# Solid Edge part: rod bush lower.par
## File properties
Author: Robert a Rhodes jr
Template: Normal.par
Last saved by: CADCIM
Revision: 11
Application: Solid Edge
Accuracy: 0.99
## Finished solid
Body 1: solid body, 4 faces, 4 edges, 0 vertices.
  Faces by surface: cylinder 2, plane 2
  Edges by curve: circle 4
Bounding box of the edges (mm): 15.000 x 15.000 x 24.000, from (-7.5, -7.5, -24) to (7.5, 7.5, 0).
Cylindrical faces by radius (mm): R6 x1, R7.5 x1
Planar faces by outward normal: +z 1, -z 1
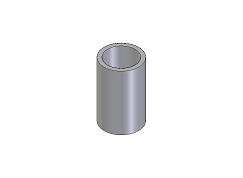
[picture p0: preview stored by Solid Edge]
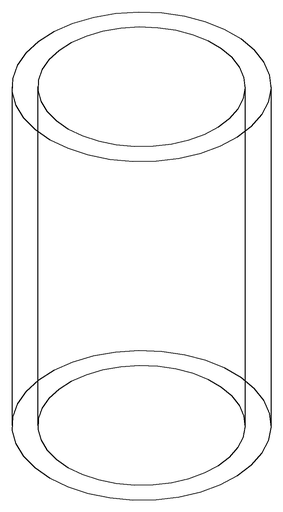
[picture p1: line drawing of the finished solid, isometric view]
